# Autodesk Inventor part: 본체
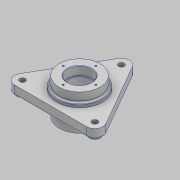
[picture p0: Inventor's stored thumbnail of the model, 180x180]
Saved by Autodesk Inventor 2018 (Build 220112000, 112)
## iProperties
Created: 2023-04
Part Number: 본체
Material: 알루미늄 6061
Document SubType Name: Modeling
Designer: home
Density: 2.7 g/cm^3
Appearance: 알루미늄 - 평지
Mass: 1219.15 g
Surface Area: 640.904 cm^2
Volume: 451.537 cm^3
Author: home
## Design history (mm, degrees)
sketch "스케치1"
  geometry: L1 (-84.87, -33)-(-13.856, 90); L2 (-71.014, -57)-(71.014, -57); L3 (13.856, 90)-(84.87, -33); C1 r 5.5 at (0, 82); C2 r 5.5 at (71.014, -41); C3 r 5.5 at (-71.014, -41); A1 r 16 centre (-71.014, -41) between (-84.87, -33) and (-71.014, -57); A2 r 16 centre (71.014, -41) between (71.014, -57) and (84.87, -33); A3 r 16 centre (0, 82) between (13.856, 90) and (-13.856, 90); 1 further point
  constraints: 6 centre point, 6 end point, 6 point on circle, 3 coincident, 3 tangent, 1 horizontal
  dimensions: "d3" = 32 diameter of A1; "d4" = 32 diameter of A2; "d5" = 32 diameter of A3; "d6" = 11 diameter of C1; "d7" = 11 diameter of C2; "d8" = 11 diameter of C3
extrude "돌출1" new body sketch "스케치1" distance "d9" = 18; taper "d10" = 0 deg
sketch "스케치2"
  geometry: L1 (-71.014, -57)-(71.014, -57) reference; L2 (84.87, -33)-(13.856, 90) reference; L3 (-13.856, 90)-(-84.87, -33) reference; L4 (0, 82)-(0, 0); C1 r 5.5 at (-71.014, -41) reference; C2 r 5.5 at (71.014, -41) reference; C3 r 5.5 at (0, 82) reference; C4 r 5.5 at (0, 82) reference; C5 r 45 at (0, 0); A1 r 16 centre (-71.014, -41) between (-84.87, -33) and (-71.014, -57) reference; A2 r 16 centre (71.014, -41) between (71.014, -57) and (84.87, -33) reference; A3 r 16 centre (0, 82) between (13.856, 90) and (-13.856, 90) reference
  constraints: 2 end point, 1 centre point, 1 coincident, 1 vertical
  dimensions: "d11" = 90 diameter of C5
extrude "돌출2" join sketch "스케치2" distance "d12" = 5; taper "d13" = 0 deg
sketch "스케치3"
  geometry: C1 r 40 at (0, 0); 1 further point
  constraints: 1 centre point, 1 coincident
  dimensions: "d14" = 80 diameter of C1
extrude "돌출3" join sketch "스케치3" distance "d15" = 18; taper "d16" = 0 deg
sketch "스케치4"
  geometry: C1 r 40 at (0, 0); 1 further point
  constraints: 1 centre point, 1 coincident
  dimensions: "d18" = 80 diameter of C1
extrude "돌출4" join sketch "스케치4" distance "d19" = 29; taper "d20" = 0 deg
fillet "모깎기1" dims "d21" = 3
sketch "스케치5"
  geometry: L1 (13.856, 90)-(84.87, -33) reference; L2 (71.014, -57)-(-71.014, -57) reference; L3 (-84.87, -33)-(-13.856, 90) reference; C1 r 43 at (0, 0) reference; C2 r 5.5 at (71.014, -41) reference; C3 r 5.5 at (-71.014, -41) reference; C4 r 5.5 at (0, 82) reference; C5 r 5.5 at (0, 82) reference; C6 r 11 at (0, 82); C7 r 11 at (-71.014, -41); C8 r 5.5 at (71.014, -41) reference; C9 r 11 at (71.014, -41); A1 r 16 centre (71.014, -41) between (71.014, -57) and (84.87, -33) reference; A2 r 16 centre (-71.014, -41) between (-84.87, -33) and (-71.014, -57) reference; A3 r 16 centre (0, 82) between (13.856, 90) and (-13.856, 90) reference; 1 further point
  constraints: 3 centre point, 3 coincident
  dimensions: "d22" = 22 diameter of C6; "d23" = 22 diameter of C7; "d24" = 22 diameter of C9
extrude "돌출5" join sketch "스케치5" distance "d25" = 4; taper "d26" = 0 deg
fillet "모깎기2" dims "d27" = 3
fillet "모깎기3" dims "d28" = 3
sketch "스케치6"
  geometry: 5 further points
hole "구멍1" sketch "스케치6" at (0, 32), (-32, 0), (0, -32), (32, 0) diameter "d30" = 3.242; stored, may be unused: countersink angle "d34" = 90 deg, drill point angle "d36" = 118 deg; dims "d31" = 8, "d32" = 4, "d33" = 2, "d35" = 10
sketch "스케치7"
  geometry: C1 r 1.621 at (0, 32) reference; C2 r 1.621 at (-32, 0) reference; C3 r 1.621 at (0, -32) reference; C4 r 1.621 at (32, 0) reference; 5 further points
  constraints: 4 coincident
hole "구멍2" sketch "스케치7" at (0, 32), (-32, 0), (0, -32), (32, 0) diameter "d38" = 3.242; stored, may be unused: countersink angle "d42" = 90 deg, drill point angle "d44" = 118 deg; dims "d39" = 8, "d40" = 4, "d41" = 2, "d43" = 10
hole "구멍3" diameter "d47" = 42; stored, may be unused: countersink angle "d51" = 90 deg, drill point angle "d53" = 118 deg; dims "d45" = 10, "d46" = 10, "d48" = 8, "d49" = 47, "d50" = 17, "d52" = 80
hole "구멍4" diameter "d56" = 42; stored, may be unused: countersink angle "d60" = 90 deg, drill point angle "d62" = 118 deg; dims "d54" = 10, "d55" = 10, "d57" = 8, "d58" = 47, "d59" = 17, "d61" = 80
fillet "모깎기4" dims "d63" = 0.6
chamfer "모따기1" distance "d64" = 1; stored, may be unused: second distance "d65" = 2, angle "d66" = 45 deg
sketch "스케치8"
  geometry: L1 (0, 0)-(0, 60); 1 further point
  constraints: 2 end point, 1 coincident, 1 vertical, 1 other
  dimensions: "d67" = 60 distance of L1.start L1.end
feature "엠보싱1" sketch "스케치8" dims "d3" = 32, "d4" = 32, "d5" = 32, "d6" = 11, "d7" = 11, "d8" = 11, "d68" = 0.5, "d69" = 0
node "솔리드1"
node "투영된 루프1"
node "절단 모서리 투영1"
